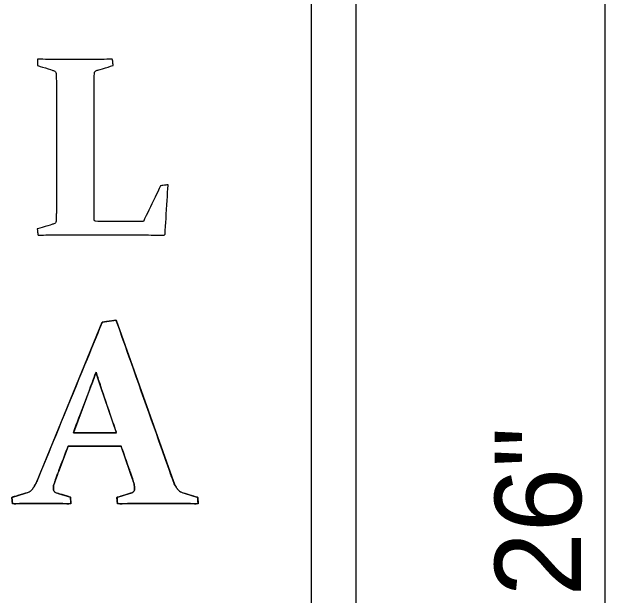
# Model space of a CAD drawing. Extents: x 60714 to 61343, y 7599 to 7998.
# Drawn here: x 61018.96 to 61038.19, y 7836.19 to 7855.08 of the extents above; entities that cross this region are included whole.
import ezdxf

# ---------------------------------------------------------------- set-up
doc = ezdxf.new("R2010")
doc.units = 0
for name, color, linetype in [('2', 7, 'Continuous'), ('Default', 7, 'Continuous'), ('SignPanel', 7, 'Continuous')]:
    doc.layers.add(name, color=color, linetype=linetype)

# ---------------------------------------------------------------- blocks, each defined once
blk = doc.blocks.new('block 6')
at = {"layer": 'Default'}
blk.add_open_spline([(836.58, -467.12), (836.58, -467.12), (836.58, -501.78), (836.58, -501.78), (836.58, -504.99), (836.61, -508.17), (836.67, -511.33), (836.67, -511.33), (853.81, -511.33), (853.81, -511.33), (853.81, -511.33), (859.81, -498.88), (859.81, -498.88), (859.81, -498.88), (862.48, -498.49), (862.48, -498.49), (862.48, -498.49), (861.39, -515.8), (861.39, -515.8), (861.39, -515.8), (861.08, -516.1), (861.08, -516.1), (853.86, -516.02), (846.81, -515.97), (839.91, -515.97), (839.91, -515.97), (829.05, -515.97), (829.05, -515.97), (824.7, -515.97), (820.66, -516.02), (816.95, -516.1), (816.95, -516.1), (816.74, -513.91), (816.74, -513.91), (816.74, -513.91), (822.17, -512.29), (822.17, -512.29), (822.9, -512.09), (823.29, -511.64), (823.35, -510.93), (823.38, -509.77), (823.4, -508.46), (823.42, -507.01), (823.43, -505.57), (823.44, -503.97), (823.44, -502.21), (823.44, -502.21), (823.44, -467.29), (823.44, -467.29), (823.44, -465.83), (823.43, -464.5), (823.42, -463.3), (823.4, -462.11), (823.38, -461.01), (823.35, -460.02), (823.32, -459.26), (822.97, -458.78), (822.3, -458.57), (822.3, -458.57), (816.87, -456.86), (816.87, -456.86), (816.87, -456.86), (816.74, -454.63), (816.74, -454.63), (820.5, -454.75), (824.86, -454.8), (829.79, -454.8), (834.88, -454.8), (839.29, -454.75), (843.03, -454.63), (843.03, -454.63), (843.25, -456.86), (843.25, -456.86), (843.25, -456.86), (837.81, -458.48), (837.81, -458.48), (837.11, -458.66), (836.73, -459.1), (836.67, -459.8), (836.64, -460.85), (836.62, -462.35), (836.6, -464.29), (836.59, -466.23), (836.58, -467.17), (836.58, -467.12)], degree=3, dxfattribs=at)
blk.add_open_spline([(836.58, -467.12), (836.58, -467.12), (836.58, -501.78), (836.58, -501.78), (836.58, -504.99), (836.61, -508.17), (836.67, -511.33), (836.67, -511.33), (853.81, -511.33), (853.81, -511.33), (853.81, -511.33), (859.81, -498.88), (859.81, -498.88), (859.81, -498.88), (862.48, -498.49), (862.48, -498.49), (862.48, -498.49), (861.39, -515.8), (861.39, -515.8), (861.39, -515.8), (861.08, -516.1), (861.08, -516.1), (853.86, -516.02), (846.81, -515.97), (839.91, -515.97), (839.91, -515.97), (829.05, -515.97), (829.05, -515.97), (824.7, -515.97), (820.66, -516.02), (816.95, -516.1), (816.95, -516.1), (816.74, -513.91), (816.74, -513.91), (816.74, -513.91), (822.17, -512.29), (822.17, -512.29), (822.9, -512.09), (823.29, -511.64), (823.35, -510.93), (823.38, -509.77), (823.4, -508.46), (823.42, -507.01), (823.43, -505.57), (823.44, -503.97), (823.44, -502.21), (823.44, -502.21), (823.44, -467.29), (823.44, -467.29), (823.44, -465.83), (823.43, -464.5), (823.42, -463.3), (823.4, -462.11), (823.38, -461.01), (823.35, -460.02), (823.32, -459.26), (822.97, -458.78), (822.3, -458.57), (822.3, -458.57), (816.87, -456.86), (816.87, -456.86), (816.87, -456.86), (816.74, -454.63), (816.74, -454.63), (820.5, -454.75), (824.86, -454.8), (829.79, -454.8), (834.88, -454.8), (839.29, -454.75), (843.03, -454.63), (843.03, -454.63), (843.25, -456.86), (843.25, -456.86), (843.25, -456.86), (837.81, -458.48), (837.81, -458.48), (837.11, -458.66), (836.73, -459.1), (836.67, -459.8), (836.64, -460.85), (836.62, -462.35), (836.6, -464.29), (836.59, -466.23), (836.58, -467.17), (836.58, -467.12)], degree=3, dxfattribs=at)
blk = doc.blocks.new('block 9')
at = {"layer": 'Default'}
for points in [[(816.99, -601.1), (839.42, -546.47), (844.29, -545.75), (863.7, -600.51)], [(835.5, -568.8), (829.34, -585.11), (844.37, -585.11), (838.84, -568.85)], [(848.97, -598.26), (846, -589.79), (827.53, -589.79), (824.34, -598.21)], [(808.08, -609.92), (807.86, -607.67), (812.67, -606.23)], [(824.02, -606.32), (828.35, -607.58), (828.48, -609.92)], [(844.78, -609.92), (844.56, -607.67), (849.01, -606.36)], [(868.38, -606.36), (872.79, -607.67), (872.93, -609.92)]]:
    blk.add_lwpolyline(points, dxfattribs=at)
for points, degree in [([(827.53, -589.79), (827.53, -589.79), (824.34, -598.21), (824.34, -598.21), (823.71, -599.86), (823.22, -601.19), (822.87, -602.2), (822.53, -603.2), (822.35, -603.98), (822.35, -604.52), (822.35, -605.02), (822.49, -605.42), (822.76, -605.69), (823.03, -605.96), (823.45, -606.17), (824.02, -606.32), (824.02, -606.32), (828.35, -607.58), (828.35, -607.58), (828.35, -607.58), (828.48, -609.92), (828.48, -609.92), (824.13, -609.83), (820.58, -609.79), (817.85, -609.79), (815, -609.79), (811.74, -609.83), (808.08, -609.92), (808.08, -609.92), (807.86, -607.67), (807.86, -607.67), (807.86, -607.67), (812.67, -606.23), (812.67, -606.23), (813.81, -605.9), (814.66, -605.35), (815.19, -604.58), (815.74, -603.82), (816.34, -602.66), (816.99, -601.1), (816.99, -601.1), (839.42, -546.47), (839.42, -546.47), (839.42, -546.47), (844.29, -545.75), (844.29, -545.75), (844.29, -545.75), (863.7, -600.51), (863.7, -600.51), (864.45, -602.61), (865.13, -604.03), (865.75, -604.76), (866.36, -605.5), (867.24, -606.03), (868.38, -606.36), (868.38, -606.36), (872.79, -607.67), (872.79, -607.67), (872.79, -607.67), (872.93, -609.92), (872.93, -609.92), (868.87, -609.83), (864.79, -609.79), (860.68, -609.79), (855.25, -609.79), (849.94, -609.83), (844.78, -609.92), (844.78, -609.92), (844.56, -607.67), (844.56, -607.67), (844.56, -607.67), (849.01, -606.36), (849.01, -606.36), (849.62, -606.18), (850.05, -605.96), (850.32, -605.69), (850.59, -605.42), (850.73, -605.02), (850.73, -604.47), (850.73, -603.87), (850.58, -603.08), (850.28, -602.11), (849.98, -601.13), (849.54, -599.85), (848.97, -598.26), (848.97, -598.26), (846, -589.79), (846, -589.79), (846, -589.79), (827.53, -589.79), (827.53, -589.79)], 3), ([(837.26, -563.94), (836.72, -565.5), (836.14, -567.12), (835.5, -568.8), (835.5, -568.8), (829.34, -585.11), (829.34, -585.11), (829.34, -585.11), (844.37, -585.11), (844.37, -585.11), (844.37, -585.11), (838.84, -568.85), (838.84, -568.85), (838.27, -567.14), (837.74, -565.5), (837.26, -563.94)], 3), ([(837.26, -563.94), (836.72, -565.5), (836.14, -567.12), (835.5, -568.8)], 2), ([(838.84, -568.85), (838.27, -567.14), (837.74, -565.5), (837.26, -563.94)], 2), ([(824.34, -598.21), (823.71, -599.86), (823.22, -601.19), (822.87, -602.2), (822.53, -603.2), (822.35, -603.98), (822.35, -604.52), (822.35, -605.02), (822.49, -605.42), (822.76, -605.69), (823.03, -605.96), (823.45, -606.17), (824.02, -606.32)], 3), ([(849.01, -606.36), (849.62, -606.18), (850.05, -605.96), (850.32, -605.69), (850.59, -605.42), (850.73, -605.02), (850.73, -604.47), (850.73, -603.87), (850.58, -603.08), (850.28, -602.11), (849.98, -601.13), (849.54, -599.85), (848.97, -598.26)], 3), ([(812.67, -606.23), (813.81, -605.9), (814.66, -605.35), (815.19, -604.58), (815.74, -603.82), (816.34, -602.66), (816.99, -601.1)], 3), ([(863.7, -600.51), (864.45, -602.61), (865.13, -604.03), (865.75, -604.76), (866.36, -605.5), (867.24, -606.03), (868.38, -606.36)], 3), ([(828.48, -609.92), (824.13, -609.83), (820.58, -609.79), (817.85, -609.79), (815, -609.79), (811.74, -609.83), (808.08, -609.92)], 3), ([(872.93, -609.92), (868.87, -609.83), (864.79, -609.79), (860.68, -609.79), (855.25, -609.79), (849.94, -609.83), (844.78, -609.92)], 3)]:
    blk.add_open_spline(points, degree=degree, dxfattribs=at)

msp = doc.modelspace()

# ---------------------------------------------------------------- linework, layer by layer
at = {"layer": '2'}
msp.add_line((61038.187, 7812.649), (61038.187, 7865.705), dxfattribs=at)
at = {"layer": 'SignPanel'}
for points in [[(61028.662, 7863.228), (61028.662, 7815.126)], [(61030.107, 7863.228), (61030.107, 7815.126)]]:
    msp.add_lwpolyline(points, dxfattribs=at)

# ---------------------------------------------------------------- block references
at = {"layer": 'SignPanel', "xscale": 0.09274527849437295, "yscale": 0.09274527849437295, "rotation": 2.962189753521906e-08}
for name in ['block 6', 'block 9']:
    msp.add_blockref(name, (60944.035, 7895.714), dxfattribs=at)

# ---------------------------------------------------------------- texts
at = {"layer": '2'}
msp.add_text('26"', height=2.8, rotation=90, dxfattribs=at).set_placement((61037.41, 7836.147))

doc.saveas('drawing.dxf')
